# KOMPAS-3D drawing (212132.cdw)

Views: Вид 1, Вид 2
Referenced files in F:\Учеба\6 семестр\Литейное производство\курсовая\: 212132.cdw
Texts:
  Царь
  POLYTEH
  Ra3,2
  Ra1,6
  Rz20
  Ст.1
  Ст.2
Dimensions and other numbers on the sheet: 1; 0,8; 20; 35; 25'; 2:1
